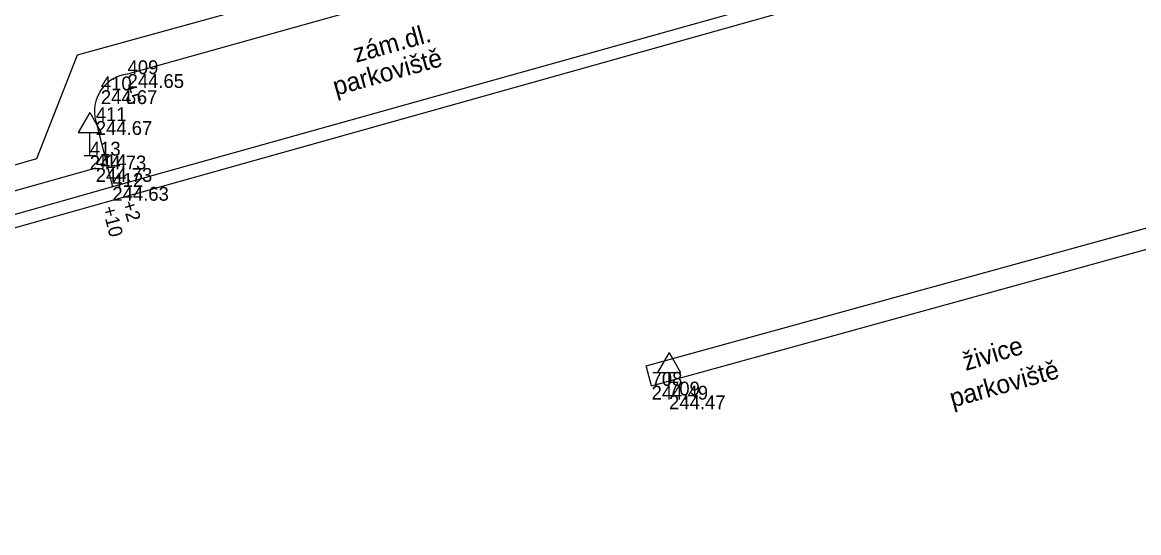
# Model space of a CAD drawing. Extents: x -599432 to -598680, y -1159407 to -1158632.
# Drawn here: x -599169.23 to -599144.96, y -1158943.99 to -1158932.91 of the extents above; entities that cross this region are included whole.
import ezdxf

# ---------------------------------------------------------------- set-up
doc = ezdxf.new("R2010")
doc.units = 0
for name, color, linetype in [('0004 VY - Body podrobné', 7, 'Continuous'), ('0005 VY - Body podrobné - čísla', 7, 'Continuous'), ('0006 VY - Body podrobné - výšky', 7, 'Continuous'), ('0024 ZA - Podezdívka', 7, 'Continuous'), ('0027 ZA - Silnice_cesta zpevněná', 7, 'Continuous'), ('0028 ZA - Silnice - nájezd na chodník', 7, 'Continuous'), ('0031 ZA - Ostatní rozhraní', 7, 'Continuous'), ('0032 TE - Popis povrchu', 7, 'Continuous'), ('0062 ZA - Doprava - dopravní značky', 7, 'Continuous'), ('0071 ZA - Zábradlí', 7, 'Continuous'), ('0073 TE - Výška obrubníků a zdí', 7, 'Continuous'), ('0074 TE - Vysvětlivky', 7, 'Continuous'), ('0652 PV - BKOM - kabely bez rozlišení', 7, 'Continuous')]:
    doc.layers.add(name, color=color, linetype=linetype)

msp = doc.modelspace()

# ---------------------------------------------------------------- linework, layer by layer
at = {"layer": '0004 VY - Body podrobné'}
for p, q in [((-599166.94, -1158934.03), (-599166.94, -1158934.03)), ((-599167.52, -1158934.38), (-599167.52, -1158934.38)), ((-599167.63, -1158935.05), (-599167.63, -1158935.05)), ((-599167.76, -1158935.8), (-599167.76, -1158935.8)), ((-599167.63, -1158936.07), (-599167.63, -1158936.07)), ((-599167.27, -1158936.48), (-599167.27, -1158936.48)), ((-599155.55, -1158940.8), (-599155.55, -1158940.8)), ((-599155.17, -1158941.01), (-599155.17, -1158941.01))]:
    msp.add_line(p, q, dxfattribs=at)
at = {"layer": '0024 ZA - Podezdívka'}
for p, q in [((-599155.67, -1158940.366), (-599143.84, -1158937.106)), ((-599155.55, -1158940.8), (-599143.72, -1158937.54)), ((-599155.55, -1158940.8), (-599155.67, -1158940.366))]:
    msp.add_line(p, q, dxfattribs=at)
at = {"layer": '0027 ZA - Silnice_cesta zpevněná'}
for p, q in [((-599137.26, -1158925.73), (-599166.94, -1158934.03)), ((-599167.63, -1158935.05), (-599167.27, -1158936.48)), ((-599167.27, -1158936.48), (-599191.05, -1158943.21))]:
    msp.add_line(p, q, dxfattribs=at)
msp.add_arc((-599166.85, -1158934.834), 0.809, 96.3552, 195.4904, dxfattribs=at)
at = {"layer": '0028 ZA - Silnice - nájezd na chodník'}
msp.add_line((-599147.65, -1158930.98), (-599167.27, -1158936.48), dxfattribs=at)
at = {"layer": '0031 ZA - Ostatní rozhraní'}
for p, q in [((-599146.961, -1158931.078), (-599167.194, -1158936.75)), ((-599167.194, -1158936.75), (-599190.974, -1158943.479))]:
    msp.add_line(p, q, dxfattribs=at)
at = {"layer": '0062 ZA - Doprava - dopravní značky'}
for p, q in [((-599167.76, -1158934.867), (-599168.01, -1158935.3)), ((-599167.76, -1158934.867), (-599167.51, -1158935.3)), ((-599168.01, -1158935.3), (-599167.51, -1158935.3)), ((-599167.76, -1158935.8), (-599167.76, -1158935.3)), ((-599167.885, -1158935.8), (-599167.635, -1158935.8)), ((-599155.17, -1158940.077), (-599155.42, -1158940.51)), ((-599155.17, -1158940.077), (-599154.92, -1158940.51)), ((-599155.42, -1158940.51), (-599154.92, -1158940.51)), ((-599155.17, -1158941.01), (-599155.17, -1158940.51)), ((-599155.295, -1158941.01), (-599155.045, -1158941.01))]:
    msp.add_line(p, q, dxfattribs=at)
at = {"layer": '0071 ZA - Zábradlí'}
msp.add_line((-599167.63, -1158936.07), (-599208.603, -1158947.666), dxfattribs=at)
at = {"layer": '0652 PV - BKOM - kabely bez rozlišení'}
msp.add_lwpolyline([(-599194.67, -1158942.89), (-599194.47, -1158942.81), (-599193.85, -1158942.64), (-599178.5, -1158938.24), (-599178, -1158938.49), (-599168.91, -1158935.86), (-599168.03, -1158933.61), (-599152.64, -1158929.37), (-599137, -1158924.99)], dxfattribs=at)

# ---------------------------------------------------------------- texts
at = {"layer": '0005 VY - Body podrobné - čísla'}
for s, p in [('409', (-599166.94, -1158934.03)), ('410', (-599167.52, -1158934.38)), ('411', (-599167.63, -1158935.05)), ('413', (-599167.76, -1158935.8)), ('414', (-599167.63, -1158936.07)), ('412', (-599167.27, -1158936.48)), ('708', (-599155.55, -1158940.8)), ('709', (-599155.17, -1158941.01))]:
    msp.add_text(s, height=0.3, dxfattribs=at).set_placement(p)
at = {"layer": '0006 VY - Body podrobné - výšky'}
for s, p in [('244.65', (-599166.94, -1158934.33)), ('244.67', (-599167.52, -1158934.68)), ('244.67', (-599167.63, -1158935.35)), ('244.73', (-599167.76, -1158936.1)), ('244.73', (-599167.63, -1158936.37)), ('244.63', (-599167.27, -1158936.78)), ('244.49', (-599155.55, -1158941.1)), ('244.47', (-599155.17, -1158941.31))]:
    msp.add_text(s, height=0.3, dxfattribs=at).set_placement(p)
at = {"layer": '0032 TE - Popis povrchu'}
for s, rotation, p in [('zám.dl.', 15.6596, (-599161.973, -1158933.785)), ('živice', 16.5788, (-599148.721, -1158940.478))]:
    msp.add_text(s, height=0.4, rotation=rotation, dxfattribs=at).set_placement(p)
at = {"layer": '0073 TE - Výška obrubníků a zdí'}
for s, rotation, p in [('+5', 286.775, (-599167.057, -1158934.281)), ('+2', 286.775, (-599167.064, -1158936.825)), ('+10', 284.3306, (-599167.49, -1158936.933))]:
    msp.add_text(s, height=0.3, rotation=rotation, dxfattribs=at).set_placement(p)
at = {"layer": '0074 TE - Vysvětlivky'}
for rotation, p in [(15.6236, (-599162.413, -1158934.502)), (15.4635, (-599149.009, -1158941.272))]:
    msp.add_text('parkoviště', height=0.4, rotation=rotation, dxfattribs=at).set_placement(p)

doc.saveas('drawing.dxf')
